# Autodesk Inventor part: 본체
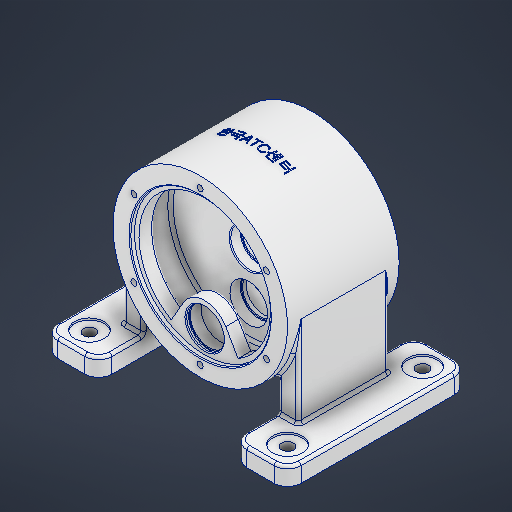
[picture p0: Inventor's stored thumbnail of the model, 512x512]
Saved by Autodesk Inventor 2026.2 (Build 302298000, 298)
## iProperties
Created: 2025-12
Part Number: 본체
Material: 알루미늄 6061
Document SubType Name: Modeling
Designer: PC2-07
Density: 2.7 g/cm^3
Appearance: 알루미늄 - 평지
Mass: 5626.44 g
Surface Area: 3057.04 cm^2
Volume: 2083.87 cm^3
Author: PC2-07
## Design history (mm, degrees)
sketch "스케치1"
  geometry: C1 r 97 at (0, 0); 1 further point
  constraints: 1 centre point, 1 coincident
  dimensions: "d0" = 194 diameter of C1
extrude "돌출1" new body sketch "스케치1" stored distance "d1" = 124; taper "d2" = 0 deg
sketch "스케치2"
  geometry: L1 (97, -62)-(-97, -62) reference; L2 (-97, -62)-(-97, 62) reference; L3 (-97, 62)-(97, 62) reference; L4 (97, 62)-(97, -62) reference; L5 (0, 62)-(0, -62); L6 (78, 62)-(78, 57); L7 (78, 57)-(73, 57); L8 (73, 57)-(73, 43); L9 (76, 40)-(84, 40); L10 (87, 37)-(87, 11); L11 (84, 8)-(22, 8); L12 (21, 7)-(21, -3.4); L13 (20.4, -4)-(19, -4); L14 (19, -4)-(19, -8); L15 (19, -8)-(84, -8); L16 (87, -11)-(87, -37); L17 (84, -40)-(76, -40); L18 (73, -43)-(73, -57); L19 (73, -57)-(78, -57); L20 (78, -57)-(78, -62); L21 (22, 8)-(21, 7); A1 r 0.6 centre (20.4, -3.4) between (20.4, -4) and (21, -3.4); A2 r 3 centre (84, 37) between (87, 37) and (84, 40); A3 r 3 centre (84, 11) between (84, 8) and (87, 11); A4 r 3 centre (84, -11) between (87, -11) and (84, -8); A5 r 3 centre (84, -37) between (84, -40) and (87, -37); A6 r 3 centre (76, -43) between (76, -40) and (73, -43); A7 r 3 centre (76, 43) between (73, 43) and (76, 40); 6 further points
  constraints: 34 end point, 14 point on circle, 14 point on line, 14 tangent, 10 perpendicular, 7 centre point, 3 equal radius, 3 vertical, 2 midpoint, 1 horizontal
  dimensions: "d3" = 156 diameter of L6 L5; "d4" = 146 diameter of L8 L5; "d5" = 174 diameter of L10 L5; "d6" = 42 diameter of L12 L5; "d7" = 38 diameter of L14 L5; "d8" = 146 diameter of L18 L5; "d9" = 156 diameter of L20 L5; "d10" = 5 distance of L6.start L6.end; "d11" = 22 distance between parallel lines of L3 L9; "d12" = 32 distance of point (87, 40) point (87, 8); "d13" = 32 distance of point (87, -8) point (87, -40); "d14" = 5 distance of L19.end L20.end; "d16" = 22 distance between parallel lines of L1 L17; "d17" = 66 distance between parallel lines of L3 L13; "d18" = 0.6 radius of A1; "d19" = 3 radius of A2; "d20" = 3 radius of A6 (derived); "d21" = 3 radius of A7 (derived); "d22" = 1 distance of L11.end point (21, 8); "d23" = 1 distance of L12.start point (21, 8) (= d22)
revolve "회전1" sketch "스케치2" stored, may be unused: angle "d24" = 90 deg
sketch "스케치4"
  geometry: L1 (78, -62)-(78, -57) reference; L2 (78, -57)-(73, -57) reference; L3 (73, -57)-(73, -43) reference; L4 (76, -40)-(84, -40) reference; L5 (87, -37)-(87, -11) reference; L6 (84, -8)-(19, -8) reference; L7 (19, -8)-(19, -4) reference; L8 (19, -4)-(20.4, -4) reference; L9 (21, -3.4)-(21, 7) reference; L10 (21, 7)-(22, 8) reference; L11 (22, 8)-(84, 8) reference; L12 (87, 11)-(87, 37) reference; L13 (84, 40)-(76, 40) reference; L14 (73, 43)-(73, 57) reference; L15 (73, 57)-(78, 57) reference; L16 (78, 57)-(78, 62) reference; L17 (78, 62)-(97, 62) reference; L18 (97, 62)-(97, -62) reference; L19 (97, -62)-(78, -62) reference; L20 (-78, -57)-(-78, -62) reference; L21 (-78, -62)-(-97, -62) reference; L22 (-97, -62)-(-97, 62) reference; L23 (-97, 62)-(-78, 62) reference; L24 (-78, 62)-(-78, 57) reference; L25 (-78, 57)-(-73, 57) reference; L26 (-76, 40)-(-84, 40) reference; L27 (-87, 37)-(-87, 11) reference; L28 (-84, 8)-(-22, 8) reference; L29 (-22, 8)-(-21, 7) reference; L30 (-21, 7)-(-21, -3.4) reference; L31 (-20.4, -4)-(-19, -4) reference; L32 (-19, -4)-(-19, -8) reference; L33 (-19, -8)-(-84, -8) reference; L34 (-87, -11)-(-87, -37) reference; L35 (-84, -40)-(-76, -40) reference; L36 (-73, -43)-(-73, -57) reference; L37 (-73, -57)-(-78, -57) reference; L38 (0, 0)-(-52.5, 0); L39 (-52.5, 0)-(-52.5, 62); L40 (-52.5, 0)-(-52.5, -62); L41 (78, -62)-(-78, -62) reference; L42 (-31.5, 57)-(-31.5, 53.95); L43 (-31.5, 53.95)-(-30.25, 53.95); L44 (-30.25, 53.95)-(-30.25, 52); L45 (-30.25, 52)-(-31.5, 52); L46 (-31.5, 52)-(-31.5, 40); L47 (-73, 57)-(-73, 43) reference; A1 r 3 centre (76, -43) between (76, -40) and (73, -43) reference; A2 r 3 centre (84, -37) between (84, -40) and (87, -37) reference; A3 r 3 centre (84, -11) between (87, -11) and (84, -8) reference; A4 r 0.6 centre (20.4, -3.4) between (20.4, -4) and (21, -3.4) reference; A5 r 3 centre (84, 11) between (84, 8) and (87, 11) reference; A6 r 3 centre (84, 37) between (87, 37) and (84, 40) reference; A7 r 3 centre (76, 43) between (73, 43) and (76, 40) reference; A8 r 3 centre (-76, 43) between (-76, 40) and (-73, 43) reference; A9 r 3 centre (-84, 37) between (-84, 40) and (-87, 37) reference; A10 r 3 centre (-84, 11) between (-87, 11) and (-84, 8) reference; A11 r 0.6 centre (-20.4, -3.4) between (-21, -3.4) and (-20.4, -4) reference; A12 r 3 centre (-84, -11) between (-84, -8) and (-87, -11) reference; A13 r 3 centre (-84, -37) between (-87, -37) and (-84, -40) reference; A14 r 3 centre (-76, -43) between (-73, -43) and (-76, -40) reference
  constraints: 16 end point, 3 vertical, 2 horizontal, 2 perpendicular, 2 point on line
  dimensions: "d32" = 52.5 distance of L38.start L38.end; "d33" = 44.5 diameter of L44 L39; "d34" = 1.95 distance of L43.end L44.end; "d35" = 12 distance of L45.end L46.end; "d36" = 42 diameter of L46 L39; "d37" = 42 diameter of L42 L39
  node "절단 모서리 투영2"
node "작업 평면2"
sketch "스케치5"
  geometry: L1 (0, 0)-(0, -52.5); L2 (-23.383, -39)-(-49.148, -83.627); L3 (0, -52.5)-(0, -97); L4 (23.383, -39)-(49.148, -83.627); C1 r 84 at (0, 0) reference; C2 r 76 at (0, 0) reference; A1 r 27 centre (0, -52.5) between (23.383, -39) and (-23.383, -39); A2 r 97 centre (0, 0) between (-49.148, -83.627) and (0, -97) reference; 2 further points
  constraints: 8 end point, 4 point on circle, 2 symmetric about line, 2 vertical, 1 centre point, 1 coincident, 1 tangent
  dimensions: "d41" = 52.5 distance of L1.start L1.end; "d42" = 54 diameter of A1; "d43" = 30 deg angle of L2 L3
extrude "돌출3" join sketch "스케치5" distance "d44" = 17; taper "d45" = 0 deg
sketch "스케치6"
  geometry: L1 (0, 0)-(-52.5, 0); L2 (-52.5, 0)-(-52.5, 62); L3 (-78, 62)-(78, 62) reference; L4 (78, -62)-(78, -57) reference; L5 (78, -57)-(73, -57) reference; L6 (73, -57)-(73, -43) reference; L7 (76, -40)-(84, -40) reference; L8 (87, -37)-(87, -11) reference; L9 (84, -8)-(19, -8) reference; L10 (19, -8)-(19, -4) reference; L11 (19, -4)-(20.4, -4) reference; L12 (21, -3.4)-(21, 7) reference; L13 (21, 7)-(22, 8) reference; L14 (22, 8)-(84, 8) reference; L15 (87, 11)-(87, 37) reference; L16 (84, 40)-(76, 40) reference; L17 (73, 43)-(73, 57) reference; L18 (73, 57)-(78, 57) reference; L19 (78, 57)-(78, 62) reference; L20 (78, 62)-(97, 62) reference; L21 (97, 62)-(97, -62) reference; L22 (97, -62)-(78, -62) reference; L23 (-78, -57)-(-78, -62) reference; L24 (-78, -62)-(-97, -62) reference; L25 (-97, -62)-(-97, 62) reference; L26 (-97, 62)-(-78, 62) reference; L27 (-78, 62)-(-78, 57) reference; L28 (-78, 57)-(-25.5, 57) reference; L29 (-25.5, 57)-(-25.5, 40) reference; L30 (-25.5, 40)-(-84, 40) reference; L31 (-87, 37)-(-87, 11) reference; L32 (-84, 8)-(-22, 8) reference; L33 (-22, 8)-(-21, 7) reference; L34 (-21, 7)-(-21, -3.4) reference; L35 (-20.4, -4)-(-19, -4) reference; L36 (-19, -4)-(-19, -8) reference; L37 (-19, -8)-(-84, -8) reference; L38 (-87, -11)-(-87, -37) reference; L39 (-84, -40)-(-76, -40) reference; L40 (-73, -43)-(-73, -57) reference; L41 (-73, -57)-(-78, -57) reference; L42 (-31.5, 57)-(-31.5, 53.95); L43 (-31.5, 53.95)-(-30.25, 53.95); L44 (-30.25, 53.95)-(-30.25, 52); L45 (-30.25, 52)-(-31.5, 52); L46 (-31.5, 52)-(-31.5, 40); A1 r 3 centre (76, -43) between (76, -40) and (73, -43) reference; A2 r 3 centre (84, -37) between (84, -40) and (87, -37) reference; A3 r 3 centre (84, -11) between (87, -11) and (84, -8) reference; A4 r 0.6 centre (20.4, -3.4) between (20.4, -4) and (21, -3.4) reference; A5 r 3 centre (84, 11) between (84, 8) and (87, 11) reference; A6 r 3 centre (84, 37) between (87, 37) and (84, 40) reference; A7 r 3 centre (76, 43) between (73, 43) and (76, 40) reference; A8 r 3 centre (-84, 37) between (-84, 40) and (-87, 37) reference; A9 r 3 centre (-84, 11) between (-87, 11) and (-84, 8) reference; A10 r 0.6 centre (-20.4, -3.4) between (-21, -3.4) and (-20.4, -4) reference; A11 r 3 centre (-84, -11) between (-84, -8) and (-87, -11) reference; A12 r 3 centre (-84, -37) between (-87, -37) and (-84, -40) reference; A13 r 3 centre (-76, -43) between (-73, -43) and (-76, -40) reference; 2 further points
  constraints: 14 end point, 4 perpendicular, 3 point on line, 2 vertical, 1 horizontal
  dimensions: "d46" = 52.5 distance of L1.start L1.end; "d47" = 12 distance of L45.end L46.end; "d48" = 1.95 distance of L43.end L44.end; "d49" = 44.5 diameter of L44 L2; "d50" = 42 diameter of L46 L2; "d51" = 42 diameter of L42 L2
revolve "회전2" sketch "스케치6" stored, may be unused: angle "d52" = 90 deg
chamfer "모따기1" distance "d53" = 1; stored, may be unused: second distance "d54" = 2, angle "d55" = 45 deg
fillet "모깎기2" dims "d56" = 3
node "작업 평면3"
sketch "스케치7"
  geometry: L1 (-75, 100)-(-135, 100); L2 (-135, 100)-(-135, -100); L3 (-135, -100)-(-75, -100); L4 (-75, -100)-(-75, 100); L5 (75, 100)-(135, 100); L6 (135, 100)-(135, -100); L7 (135, -100)-(75, -100); L8 (75, -100)-(75, 100); 3 further points
  constraints: 16 end point, 4 parallel, 2 horizontal, 2 horizontal alignment, 2 midpoint, 2 perpendicular
  dimensions: "d58" = 60 distance of L5.start L5.end; "d59" = 60 distance of L1.start L1.end; "d60" = 75 distance from line of L4 point (0, 0); "d61" = 75 distance from line of L8 point (0, 0); "d62" = 200 distance of L1.end L2.end; "d63" = 200 distance of L5.end L6.end
extrude "돌출4" join sketch "스케치7" distance "d64" = 20; taper "d65" = 0 deg
fillet "모깎기3" dims "d66" = 15
sketch "스케치8"
  geometry: L1 (135, 85)-(135, -85) reference; L2 (120, -100)-(90, -100) reference; L3 (75, -85)-(75, 85) reference; L4 (90, 100)-(120, 100) reference; L5 (-75, 85)-(-75, -85) reference; L6 (-90, -100)-(-120, -100) reference; L7 (-135, -85)-(-135, 85) reference; L8 (-120, 100)-(-90, 100) reference; C1 r 16.5 at (110, -75); C2 r 16.5 at (-110, -75); C3 r 16.5 at (-110, 75); C4 r 16.5 at (110, 75); A1 r 15 centre (120, 85) between (135, 85) and (120, 100) reference; A2 r 15 centre (120, -85) between (120, -100) and (135, -85) reference; A3 r 15 centre (90, -85) between (75, -85) and (90, -100) reference; A4 r 15 centre (90, 85) between (90, 100) and (75, 85) reference; A5 r 15 centre (-90, 85) between (-75, 85) and (-90, 100) reference; A6 r 15 centre (-90, -85) between (-90, -100) and (-75, -85) reference; A7 r 15 centre (-120, -85) between (-135, -85) and (-120, -100) reference; A8 r 15 centre (-120, 85) between (-120, 100) and (-135, 85) reference; 1 further point
  constraints: 4 centre point
  dimensions: "d67" = 150 distance of C1.centre C4.centre; "d68" = 75 vertical distance of point (0, 0) C1.centre; "d69" = 110 horizontal distance of point (0, 0) C1.centre; "d70" = 220 distance of C2.centre C1.centre; "d71" = 33 diameter of C1; "d72" = 33 diameter of C4; "d73" = 33 diameter of C3; "d74" = 33 diameter of C2; "d75" = 150 distance of C3.centre C2.centre; "d76" = 75 vertical distance of point (0, 0) C3.centre; "d77" = 110 horizontal distance of point (0, 0) C3.centre; "d78" = 110 horizontal distance of point (0, 0) C4.centre
extrude "돌출5" cut sketch "스케치8" distance "d79" = 2; taper "d80" = 0 deg
sketch "스케치9"
  geometry: C1 r 16.5 at (0, 0) reference; C2 r 6.75 at (0, 0); C3 r 16.5 at (0, 150) reference; C4 r 6.75 at (0, 150); C5 r 16.5 at (-220, 150) reference; C6 r 6.75 at (-220, 150); C7 r 16.5 at (-220, 0) reference; C8 r 6.75 at (-220, 0); 1 further point
  constraints: 4 centre point, 4 coincident
  dimensions: "d81" = 13.5 diameter of C8; "d82" = 13.5 diameter of C2; "d83" = 13.5 diameter of C4; "d84" = 13.5 diameter of C6
extrude "돌출6" cut sketch "스케치9" extent not by distance; stored distance "d85" = 0; taper "d86" = 0 deg
sketch "스케치10"
  geometry: L1 (75, 85)-(75, -85) reference; L2 (75, 50)-(97, 50); L3 (97, 50)-(97, -50); L4 (97, -50)-(75, -50); L5 (135, 85)-(135, -85) reference; L6 (120, -100)-(90, -100) reference; L7 (75, -85)-(75, 85) reference; L8 (90, 100)-(120, 100) reference; L9 (-75, 85)-(-75, -85) reference; L10 (-90, -100)-(-120, -100) reference; L11 (-135, -85)-(-135, 85) reference; L12 (-120, 100)-(-90, 100) reference; L13 (-75, 50)-(-97, 50); L14 (-97, 50)-(-97, -50); L15 (-97, -50)-(-75, -50); C1 r 16.5 at (110, 75) reference; C2 r 16.5 at (110, -75) reference; C3 r 16.5 at (-110, -75) reference; C4 r 16.5 at (-110, 75) reference; A1 r 15 centre (120, 85) between (135, 85) and (120, 100) reference; A2 r 15 centre (120, -85) between (120, -100) and (135, -85) reference; A3 r 15 centre (90, -85) between (75, -85) and (90, -100) reference; A4 r 15 centre (90, 85) between (90, 100) and (75, 85) reference; A5 r 15 centre (-90, 85) between (-75, 85) and (-90, 100) reference; A6 r 15 centre (-90, -85) between (-90, -100) and (-75, -85) reference; A7 r 15 centre (-120, -85) between (-135, -85) and (-120, -100) reference; A8 r 15 centre (-120, 85) between (-120, 100) and (-135, 85) reference; 3 further points
  constraints: 12 end point, 4 perpendicular, 4 point on line, 2 horizontal, 2 horizontal alignment, 2 midpoint
  dimensions: "d87" = 100 distance of L13.end L14.end; "d88" = 22 distance of L2.start L2.end; "d89" = 22 distance of L13.start L13.end; "d90" = 100 distance of L2.end L3.end
extrude "돌출7" join sketch "스케치10" stored distance "d91" = 100; taper "d92" = 0 deg
sketch "스케치11" dims "d93" = 170
  geometry: C1 r 97 at (0, 0) reference; 3 further points
  constraints: 2 vertical alignment, 1 coincident, 2 other
hole "구멍1" sketch "스케치11" at (0, 85) diameter "d94" = 6.647; stored, may be unused: countersink angle "d98" = 90 deg, drill point angle "d100" = 118 deg; dims "d95" = 16, "d96" = 4, "d97" = 2, "d99" = 18
sketch "스케치12"
  geometry: L1 (78, 61)-(79, 62) reference; L2 (79, 62)-(81.677, 62) reference; L3 (81.677, 62)-(81.677, 44) reference; L4 (81.677, 44)-(85, 42.003) reference; L5 (85, 42.003)-(88.323, 44) reference; L6 (88.323, 44)-(88.323, 62) reference; L7 (88.323, 62)-(97, 62) reference; L8 (97, 62)-(97, -62) reference; L9 (97, -62)-(88.323, -62) reference; L10 (88.323, -62)-(88.323, -44) reference; L11 (88.323, -44)-(85, -42.003) reference; L12 (85, -42.003)-(81.677, -44) reference; L13 (81.677, -44)-(81.677, -62) reference; L14 (81.677, -62)-(79, -62) reference; L15 (79, -62)-(78, -61) reference; L16 (78, -61)-(78, -57) reference; L17 (78, -57)-(73, -57) reference; L18 (73, -57)-(73, -43) reference; L19 (76, -40)-(84, -40) reference; L20 (87, -37)-(87, -11) reference; L21 (84, -8)-(19, -8) reference; L22 (19, -8)-(19, -4) reference; L23 (19, -4)-(20.4, -4) reference; L24 (21, -3.4)-(21, 7) reference; L25 (21, 7)-(22, 8) reference; L26 (22, 8)-(84, 8) reference; L27 (87, 11)-(87, 37) reference; L28 (84, 40)-(76, 40) reference; L29 (73, 43)-(73, 57) reference; L30 (73, 57)-(78, 57) reference; L31 (78, 57)-(78, 61) reference; L32 (-74.75, 52)-(-73.5, 52) reference; L33 (-73.5, 52)-(-73.5, 40) reference; L34 (-73.5, 40)-(-84, 40) reference; L35 (-87, 37)-(-87, 11) reference; L36 (-84, 8)-(-22, 8) reference; L37 (-22, 8)-(-21, 7) reference; L38 (-21, 7)-(-21, -3.4) reference; L39 (-20.4, -4)-(-19, -4) reference; L40 (-19, -4)-(-19, -8) reference; L41 (-19, -8)-(-84, -8) reference; L42 (-87, -11)-(-87, -37) reference; L43 (-84, -40)-(-76, -40) reference; L44 (-73, -43)-(-73, -57) reference; L45 (-73, -57)-(-78, -57) reference; L46 (-78, -57)-(-78, -61) reference; L47 (-78, -61)-(-79, -62) reference; L48 (-79, -62)-(-81.677, -62) reference; L49 (-81.677, -62)-(-81.677, -44) reference; L50 (-81.677, -44)-(-85, -42.003) reference; L51 (-85, -42.003)-(-88.323, -44) reference; L52 (-88.323, -44)-(-88.323, -62) reference; L53 (-88.323, -62)-(-97, -62) reference; L54 (-97, -62)-(-97, 62) reference; L55 (-97, 62)-(-88.323, 62) reference; L56 (-88.323, 62)-(-88.323, 44) reference; L57 (-88.323, 44)-(-85, 42.003) reference; L58 (-85, 42.003)-(-81.677, 44) reference; L59 (-81.677, 44)-(-81.677, 62) reference; L60 (-81.677, 62)-(-79, 62) reference; L61 (-79, 62)-(-78, 61) reference; L62 (-78, 61)-(-78, 57) reference; L63 (-78, 57)-(-74.5, 57) reference; L64 (-74.5, 57)-(-73.5, 56) reference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; A1 r 3 centre (76, -43) between (76, -40) and (73, -43) reference; A2 r 3 centre (84, -37) between (84, -40) and (87, -37) reference; A3 r 3 centre (84, -11) between (87, -11) and (84, -8) reference; A4 r 0.6 centre (20.4, -3.4) between (20.4, -4) and (21, -3.4) reference; A5 r 3 centre (84, 11) between (84, 8) and (87, 11) reference; A6 r 3 centre (84, 37) between (87, 37) and (84, 40) reference; A7 r 3 centre (76, 43) between (73, 43) and (76, 40) reference; A8 r 3 centre (-84, 37) between (-84, 40) and (-87, 37) reference; A9 r 3 centre (-84, 11) between (-87, 11) and (-84, 8) reference; A10 r 0.6 centre (-20.4, -3.4) between (-21, -3.4) and (-20.4, -4) reference; A11 r 3 centre (-84, -11) between (-84, -8) and (-87, -11) reference; A12 r 3 centre (-84, -37) between (-87, -37) and (-84, -40) reference; A13 r 3 centre (-76, -43) between (-73, -43) and (-76, -40) reference; A14 r 3 centre (-28.5, 43) between (-28.5, 40) and (-25.5, 43) reference; A15 r 0.6 centre (-32.1, -3.4) between (-32.1, -4) and (-31.5, -3.4)
  constraints: 12 end point, 4 point on line, 3 perpendicular, 2 point on circle, 2 tangent, 2 vertical, 1 centre point, 1 parallel
  dimensions: "d104" = 52.5 distance of L77.start L77.end; "d105" = 42 diameter of L80 L78; "d106" = 66 distance between parallel lines of L83 L81; "d107" = 38 diameter of L82 L78; "d108" = 0.6 radius of A15
revolve "회전3" sketch "스케치12" stored, may be unused: angle "d109" = 90 deg
sketch "스케치13"
  geometry: L1 (75, -120)-(75, -61.514) reference; L2 (-75, -61.514)-(-75, -120) reference; L3 (-75, -120)-(-135, -120) reference; L4 (-135, -120)-(-135, -100) reference; L5 (-135, -100)-(-97, -100) reference; L6 (-97, -100)-(-97, 0) reference; L7 (97, 0)-(97, -100) reference; L8 (97, -100)-(135, -100) reference; L9 (135, -100)-(135, -120) reference; L10 (135, -120)-(75, -120) reference; L11 (-75, -112)-(-36.6, -89.83); C1 r 21 at (0, -52.5) reference; C2 r 21 at (0, 0) reference; A1 r 97 centre (0, 0) between (-75, -61.514) and (75, -61.514) reference; A2 r 97 centre (0, 0) between (97, 0) and (-97, 0) reference; 1 further point
  constraints: 2 end point, 1 point on circle, 1 point on line
  dimensions: "d110" = 60 deg angle of L11 L2; "d111" = 8 distance from line of L3 L11.start
extrude "돌출8" join sketch "스케치13" stored distance "d112" = 12; taper "d113" = 0 deg
fillet "모깎기4" dims "d114" = 3
fillet "모깎기5" dims "d115" = 3
fillet "모깎기6" dims "d116" = 3
fillet "모깎기7" dims "d117" = 3
fillet "모깎기8" dims "d118" = 3
fillet "모깎기9" dims "d119" = 3
sketch "스케치14"
  geometry: 2 further points
  constraints: 2 coincident, 1 other
feature "엠보싱1" sketch "스케치14" dims "d1" = 124, "d14" = 5, "d120" = 0.5, "d121" = 0
node "솔리드1"
pattern_circular "원형 패턴1" dims angle "d102" = 360 deg
mirror "미러1"
mirror "미러2"
node "절단 모서리 투영1"
node "절단 모서리 투영3"
node "절단 모서리 투영4"
node "절단 모서리 투영5"
node "절단 모서리 투영6"
node "절단 모서리 투영7"
node "절단 모서리 투영8"
other parameters: "d26" = 54, "d40" = -22
